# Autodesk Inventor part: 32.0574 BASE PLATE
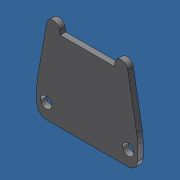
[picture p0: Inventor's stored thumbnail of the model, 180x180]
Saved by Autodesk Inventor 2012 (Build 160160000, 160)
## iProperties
Created: 2013-04
Part Number: 32.0574 BASE PLATE
Material: Stainless Steel
Document SubType Name: Modeling
Designer: Admin
Density: 8.08 g/cm^3
Mass: 52.8657 g
Surface Area: 50.5589 cm^2
Volume: 6.54279 cm^3
Author: Admin
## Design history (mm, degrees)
feature "Base1"
body "Solid1"
